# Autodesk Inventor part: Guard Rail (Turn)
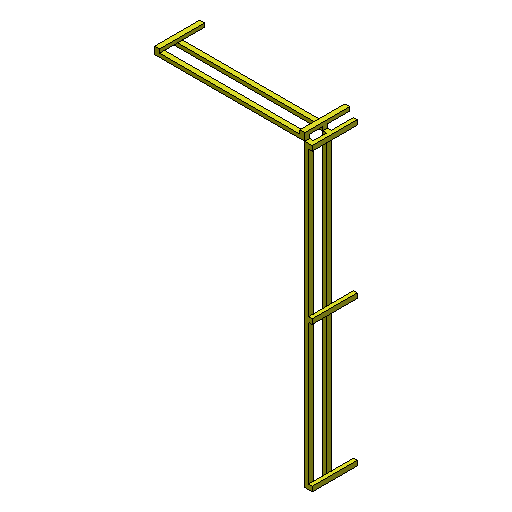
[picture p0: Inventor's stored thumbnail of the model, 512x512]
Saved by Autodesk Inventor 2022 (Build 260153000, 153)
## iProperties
Created: 2009-09
Part Number: Guard Rail (Turn)
Document SubType Name: Modeling
Designer: Autodesk, Inc.
Density: 1 g/cm^3
Material: 一般
Sheet Metal Rule: Default
Appearance: 滑らか - 黄
Key Parameters: Length=6101.100 mm;Height=914.400 mm;TurnLength=3050.500 mm;Angle=90.00 deg;
ConnectorClass: SafetyEquipment
family_type: GuardRail
Title: Guard Rail (Turn)
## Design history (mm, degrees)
sketch "Sketch1"
  geometry: L1 (0, 0)-(-76.2, 0); L2 (-76.2, 0)-(-76.2, 99.1); L3 (-76.2, 99.1)-(0, 99.1); L4 (0, 99.1)-(0, 0)
  constraints: 8 end point, 2 parallel, 1 horizontal, 1 perpendicular
  dimensions: "d0" = 99.1 distance of L1.end L2.end (= PillarLength); "d1" = 76.2 distance of L1.start L1.end (= PillarWidth)
extrude "Extrusion1" new body sketch "Sketch1" distance "d2" = 914.4 (derived); taper "d3" = 0 deg
sketch "Sketch5"
  geometry: L1 (0, 0)-(-99.1, 0); L2 (-99.1, 0)-(-99.1, 6101.1); L3 (-99.1, 6101.1)-(0, 6101.1); L4 (0, 6101.1)-(0, 0)
  constraints: 8 end point, 2 parallel, 1 horizontal, 1 perpendicular
  dimensions: "d8" = 6101.1 distance of L3.end L1.start (derived); "d9" = 99.1 distance of L2.end L3.end (= PillarLength)
extrude "Extrusion2" join sketch "Sketch5" distance "d10" = 76.2 (= PillarWidth); taper "d11" = 0 deg
pattern_linear "Rectangular Pattern1" dims "d14" = 365.76 (= ArrayLevel)
pattern_linear "Rectangular Pattern2" dims "d17" = 2950
workaxis "Work Axis1"
workplane "Work Plane2"
  workplane "Work Plane1"
sketch "Sketch6"
  geometry: L1 (-99.1, 0)-(-99.1, 0) reference; L2 (-99.1, 0)-(0, 0) reference; L3 (0, 0)-(-99.1, 0); L4 (-99.1, 0)-(-99.1, 76.2); L5 (-99.1, 76.2)-(0, 76.2); L6 (0, 76.2)-(0, 0); L7 (0, 0)-(0, 0) reference; L8 (0, 0)-(-99.1, 0) reference; 8 further points
  constraints: 8 end point, 2 parallel, 1 horizontal, 1 perpendicular
  dimensions: "d20" = 76.2 distance of L5.end L2.end (= PillarWidth); "d21" = 99.1 distance of L4.end L5.end (= PillarLength)
extrude "Extrusion3" join sketch "Sketch6" distance "d22" = 3050.5 (derived); taper "d23" = 0 deg
pattern_linear "Rectangular Pattern3" dims "d26" = 365.76 (= ArrayLevel)
sketch "Sketch7"
  geometry: L1 (3050.5, 0)-(3050.5, 99.1) reference; L2 (0, 99.1)-(3050.5, 99.1) reference; L3 (0, 0)-(3050.5, 0) reference; L4 (0, 99.1)-(99.1, 99.1); L5 (99.1, 99.1)-(99.1, -815.3); L6 (99.1, -815.3)-(0, -815.3); L7 (0, -815.3)-(0, 99.1); L8 (0, 99.1)-(0, 0) reference; 1 further point
  constraints: 8 end point, 2 parallel, 1 horizontal, 1 perpendicular
  dimensions: "d27" = 99.1 distance of L4.start L4.end (= PillarLength); "d28" = 914.4 distance of L4.end L5.end (derived)
extrude "Extrusion4" join sketch "Sketch7" distance "d29" = 76.2 (= PillarWidth); taper "d30" = 0 deg
sketch "Sketch8"
  geometry: L1 (2951.4, 0)-(2951.4, 99.1) reference; L2 (2951.4, 99.1)-(0, 99.1) reference; L3 (0, 99.1)-(0, 0) reference; L4 (2951.4, 0)-(0, 0) reference; L5 (0, 0)-(99.1, 0); L6 (99.1, 0)-(99.1, 914.4); L7 (99.1, 914.4)-(0, 914.4); L8 (0, 914.4)-(0, 0); 1 further point
  constraints: 8 end point, 2 parallel, 1 horizontal, 1 perpendicular
  dimensions: "d34" = 99.1 distance of L3.end L5.end (= PillarLength); "d35" = 914.4 distance of L7.end L3.end (derived)
extrude "Extrusion5" join sketch "Sketch8" distance "d36" = 76.2 (= PillarWidth); taper "d37" = 0 deg
sketch "Sketch9"
  geometry: L1 (99.1, 6101.1)-(99.1, 3049.1) reference; L2 (0, 3049.1)-(0, 6101.1) reference; L3 (464.86, 6101.1)-(464.86, 3049.1) reference; L4 (365.76, 3049.1)-(365.76, 6101.1) reference; L5 (0, 6101.1)-(914.4, 6101.1); L6 (914.4, 6101.1)-(914.4, 6002); L7 (914.4, 6002)-(0, 6002); L8 (0, 6002)-(0, 6101.1); L9 (365.76, 99.1)-(464.86, 99.1) reference; L10 (0, 99.1)-(99.1, 99.1) reference; L11 (464.86, 2950)-(365.76, 2950) reference; L12 (464.86, 2950)-(464.86, 99.1) reference; L13 (365.76, 3049.1)-(464.86, 3049.1) reference; L14 (99.1, 2950)-(0, 2950) reference; L15 (99.1, 2950)-(99.1, 99.1) reference; L16 (0, 3049.1)-(99.1, 3049.1) reference; L17 (365.76, 99.1)-(365.76, 2950) reference; L18 (0, 99.1)-(0, 2950) reference; L19 (365.76, 6101.1)-(464.86, 6101.1) reference; L20 (0, 6101.1)-(99.1, 6101.1) reference; L21 (0, 6101.1)-(99.1, 6101.1) reference; L22 (0, 3049.1)-(0, 6101.1) reference; 1 further point
  constraints: 8 end point, 2 collinear, 2 parallel, 1 horizontal, 1 perpendicular
  dimensions: "d41" = 99.1 distance of L7.end L5.start (= PillarLength); "d42" = 914.4 distance of L5.start L5.end (derived)
extrude "Extrusion6" join sketch "Sketch9" distance "d43" = 76.2 (= PillarWidth); taper "d44" = 0 deg
node "Connector_Work Plane1"
node "Connector_Work Plane2"
node "Connector1_Work Axis1"
node "Connector1_Work Axis2"
node "Connector1_Work Axis3"
node "Connector1_Work Point1"
node "Connector2_Work Axis1"
  workaxis "Work Axis6"
node "Connector2_Work Axis2"
  workaxis "Work Axis8"
node "Connector2_Work Point1"
workpoint "Work Point8"
node "Landing Surface"
workpoint "Work Point9"
workpoint "Work Point10"
workpoint "Work Point11"
node "Insertion Point2"
node "Connector3"
node "Connector4"
body "Solid1"
pattern_linear "Rectangular Pattern4" dims "d40" = 2950
sketch "Sketch10"
  geometry: L1 (-365.76, 0)-(-464.86, 0) reference; L2 (-365.76, 76.2)-(-365.76, 0) reference; L3 (-365.76, 76.2)-(-99.1, 76.2) reference; L4 (-99.1, 0)-(-99.1, 76.2) reference; L5 (0, 0)-(-99.1, 0) reference; L6 (0, 152.4)-(0, 0) reference; L7 (0, 152.4)-(-914.4, 152.4) reference; L8 (-914.4, 76.2)-(-914.4, 152.4) reference; L9 (-914.4, 76.2)-(-464.86, 76.2) reference; L10 (-464.86, 0)-(-464.86, 76.2) reference; 2 further points
  constraints: 1 coincident
sketch "Sketch11"
  geometry: L1 (0, 0)-(76.2, 0) reference; L2 (76.2, 914.4)-(76.2, 0) reference; L3 (76.2, 914.4)-(-76.2, 914.4) reference; L4 (-76.2, 914.4)-(-76.2, 815.3) reference; L5 (0, 815.3)-(-76.2, 815.3) reference; L6 (0, 815.3)-(0, 548.64) reference; L7 (0, 548.64)-(-76.2, 548.64) reference; L8 (-76.2, 548.64)-(-76.2, 449.54) reference; L9 (0, 449.54)-(-76.2, 449.54) reference; L10 (0, 449.54)-(0, 0) reference; 1 further point
  constraints: 1 coincident
sketch "Sketch12"
  geometry: L1 (-76.2, 99.1)-(-76.2, 0) reference; L2 (0, 0)-(-76.2, 0) reference; L3 (0, 0)-(0, 99.1) reference; L4 (0, 99.1)-(-76.2, 99.1) reference; 4 further points
  constraints: 1 coincident
node "Projected Loop1"
node "Projected Loop2"
node "Projected Loop3"
node "Projected Loop4"
node "Projected Loop5"
other parameters: "PillarLength" = 99.1 [user parameter; used in 6 equation terms], "PillarWidth" = 76.2 [user parameter; used in 6 equation terms], "ArrayLevel" = 365.76 [user parameter; used in 3 equation terms], "d18" = 90 deg (= Angle1), "d19" = 90 deg, "Angle1" = 90 deg (= AngleTurn) [user parameter; used in 1 equation term], "AngleTurn" = 90 deg [user parameter; used in 2 equation terms], "Thickness" = 3.048 (derived), "KFactor" = 4.4, "BendRadius" = 3.048 (= Thickness), "BendReliefWidth" = 3.048 (= Thickness), "BendReliefDepth" = 1.524 (= 0.5 x Thickness), "CornerReliefSize" = 12.192 (= 4 x Thickness), "SeamGap" = 0.01, "MinimumRemnant" = 6.096 (= 2 x Thickness), "TransitionRadius" = 3.048 (= BendRadius), "JacobiRadiusSize" = 3.048 (= Thickness), "GapSize" = 3.048 (= Thickness), "d77" = -3202.9, "d78" = 6177.3, "d79" = -464.86, "d80" = 0, "d81" = 0, "d82" = -180 deg, "d83" = -76.2, "d84" = 0, "d85" = -464.86, "d86" = 0, "d87" = 0, "d88" = 90 deg
